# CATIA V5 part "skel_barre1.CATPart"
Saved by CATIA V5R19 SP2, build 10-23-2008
Part number: skel_barre1
Bounding box of the stored display mesh (mm): x 0 to 20, y 25.773 to 31.173, z 10.42 to 10.42
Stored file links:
  E:\TRAVAIL\IAO\skel_barre1.CATPart
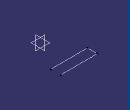
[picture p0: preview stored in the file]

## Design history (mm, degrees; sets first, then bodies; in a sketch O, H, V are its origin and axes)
Body1 (main body)
  Point1 "Point.E": stored without definition
  Point2 "Point.A": stored without definition
  Line1 "barre_1": type PtPt, FirstPoint Point1, SecondPoint Point2
  Plane1 "Plan_ref": stored without definition
  Point3 "Point.E": stored without definition
  Line2 "axe_pivot_bati_barre1": type Normal, RefPoint Point3, RefSkin Plane1, Start 0, End 20
  Plane2 "Plan_ref": stored without definition
  Point4 "Point.A": stored without definition
  Line3 "axe_pivot_barre1_barre2": type Normal, RefPoint Point4, RefSkin Plane2, Start 0, End 20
